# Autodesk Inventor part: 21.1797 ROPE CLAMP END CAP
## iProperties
Created: 2007-01
Part Number: 21.1797 ROPE CLAMP END CAP
Document SubType Name: Modeling
Designer: Andy Moles
Material: ABS Plastic
Density: 1.06 g/cm^3
Author: Andy Moles
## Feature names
1. Extrusion1
2. Fillet1
3. Fillet2
4. Extrusion2
5. Extrusion3
6. Extrusion4
